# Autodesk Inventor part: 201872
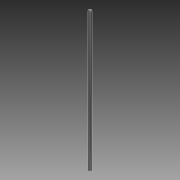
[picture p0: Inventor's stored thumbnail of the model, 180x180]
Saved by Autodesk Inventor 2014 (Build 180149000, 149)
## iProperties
Created: 2007-10
Part Number: 201872
Document SubType Name: Modeling
Designer: TH
Density: 7.85 g/cm^3
Mass: 137.687 g
Surface Area: 88.4986 cm^2
Volume: 17.5397 cm^3
Material: Steel
Description: PIVOT ROD
Appearance: Steel - Polished
Component Category: Lower Component
Author: TH
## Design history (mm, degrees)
sketch "Sketch1"
  geometry: C1 r 4 at (0, 0); 1 further point
  constraints: 1 centre point, 1 coincident
  dimensions: "d0" = 8 diameter of C1
extrude "Extrusion1" new body sketch "Sketch1" stored distance "d1" = 349.4; taper "d2" = 0 deg
chamfer "Chamfer1" distance "d3" = 1; stored, may be unused: second distance "d4" = 2, angle "d5" = 45 deg
body "Solid1"
